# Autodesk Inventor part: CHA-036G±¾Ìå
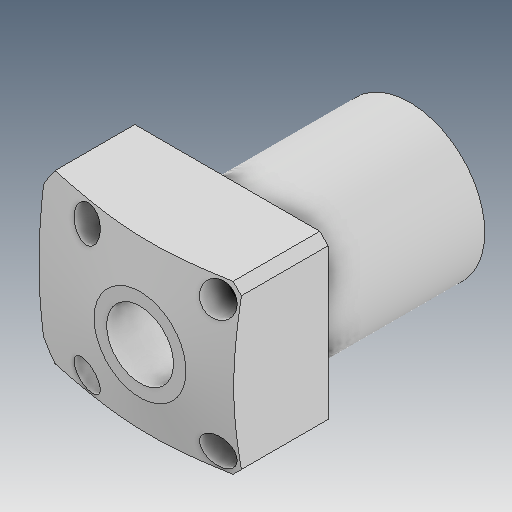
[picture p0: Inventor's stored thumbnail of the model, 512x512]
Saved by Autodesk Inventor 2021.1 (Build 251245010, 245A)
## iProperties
Created: 2019-12
Part Number: CHA-036G±¾Ìå
Material: Ogólny
Document SubType Name: Modeling
Designer: user
Density: 1 g/cm^3
Appearance: Domyślna
Author: user
Revision Number: ÈÎºÎ
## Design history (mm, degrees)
feature "ÊäÈë1"
node "Bryła1"
